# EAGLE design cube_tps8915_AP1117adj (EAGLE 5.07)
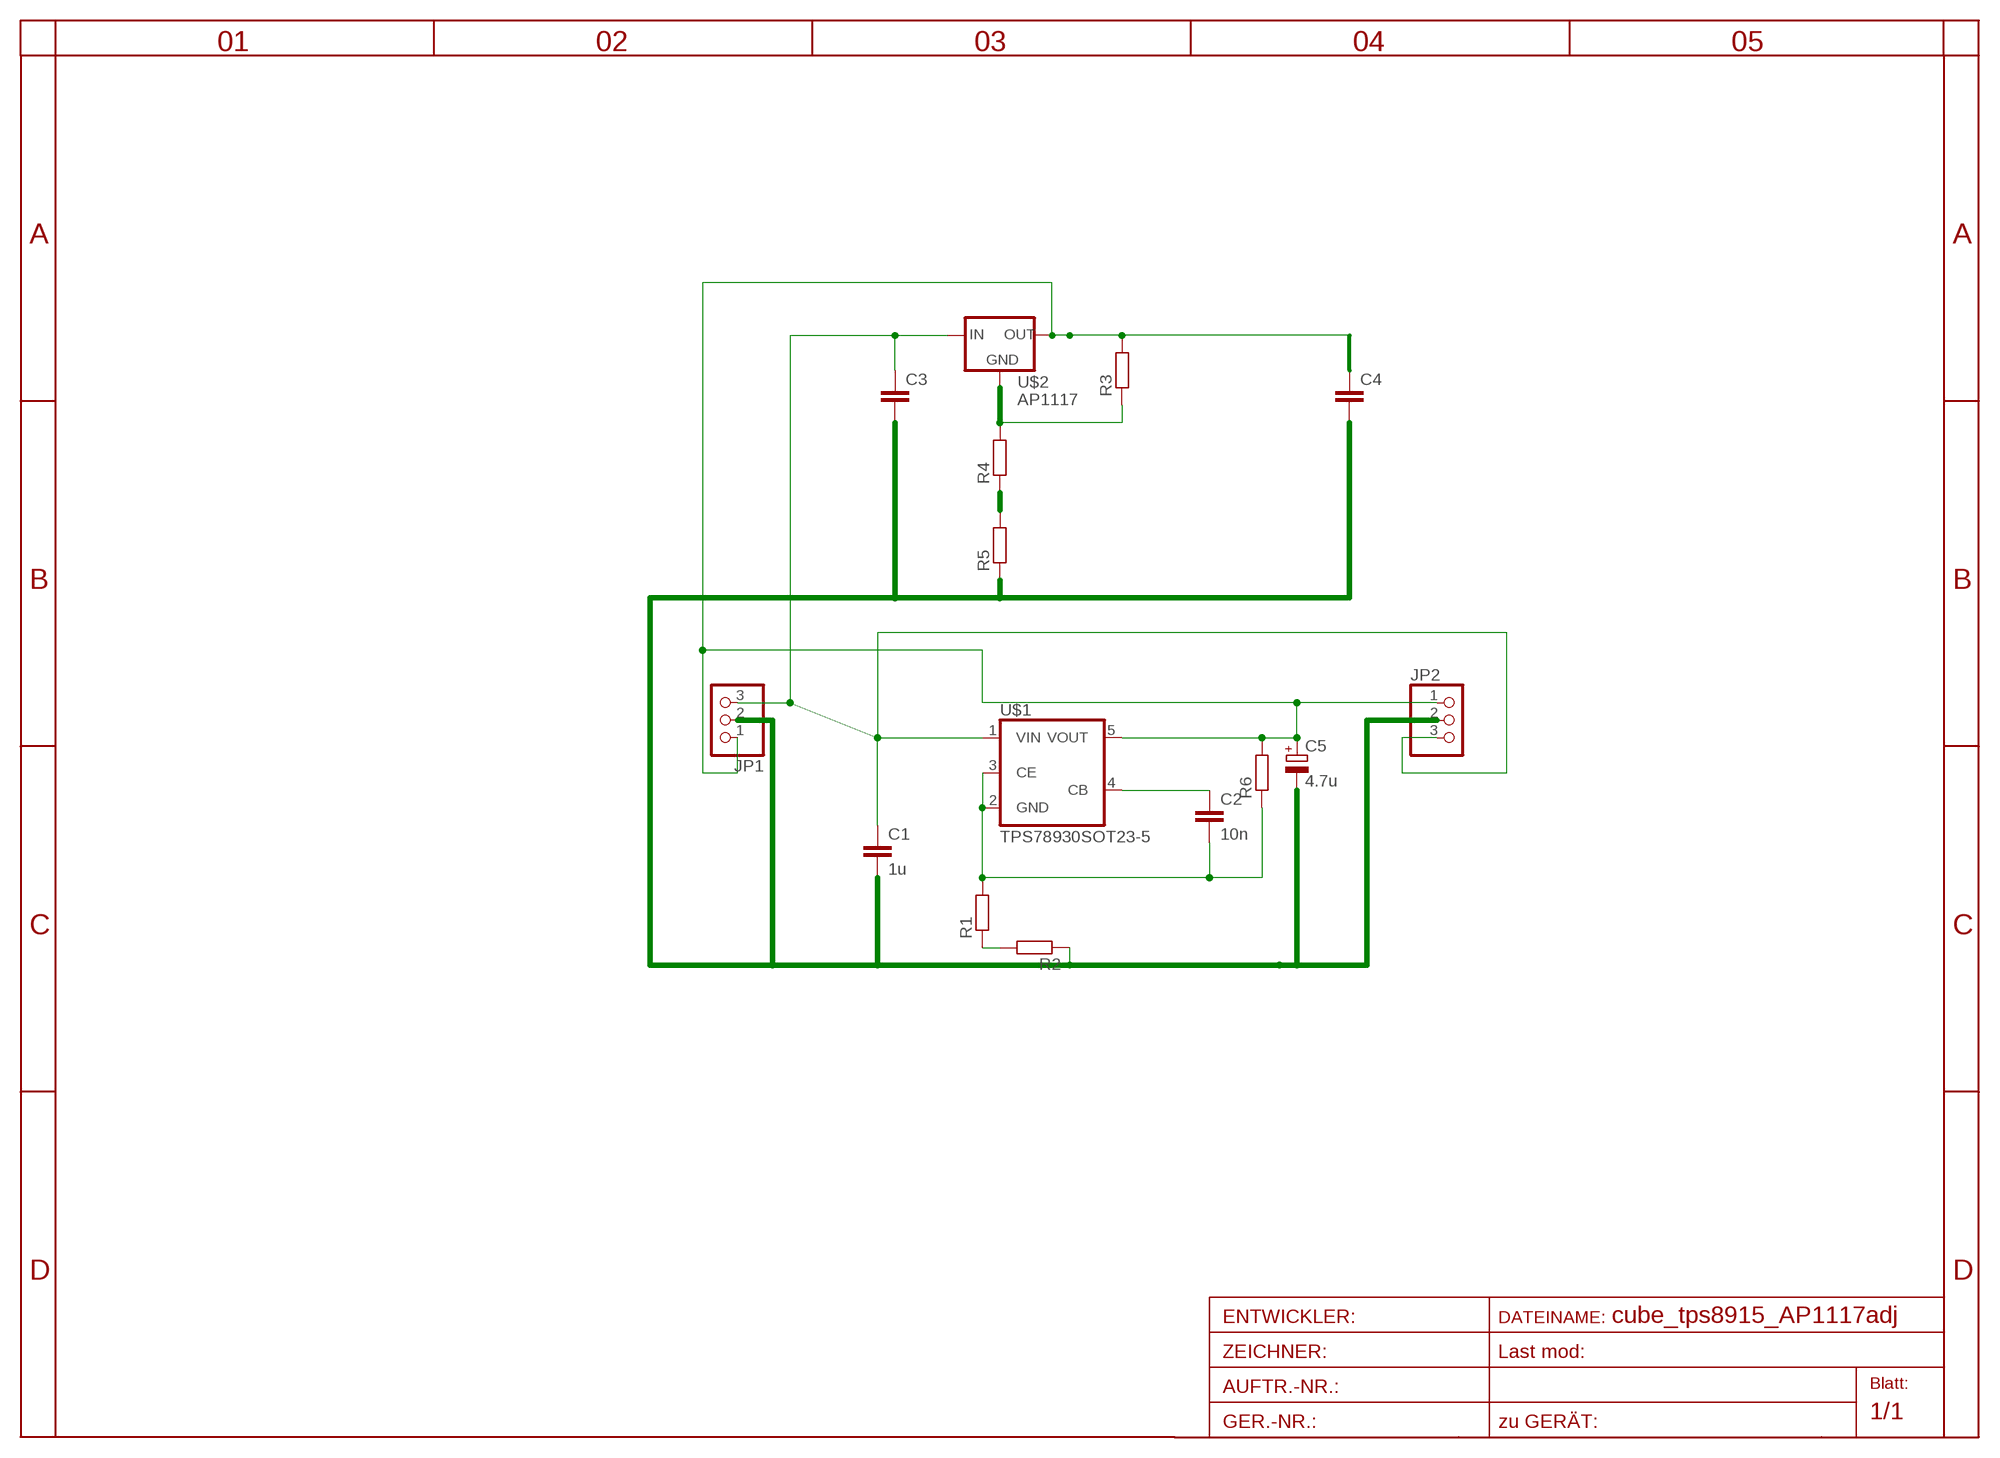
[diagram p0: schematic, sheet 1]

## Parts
C1  1u  C-EUC1206  [C1206]
C2  10n  C-EUC0805  [C0805]
C3  C-EUC1206  [C1206]
C4  C-EUC1206  [C1206]
C5  4.7u  CPOL-EUSMCA  [SMC_A]
JP1  PINHD-1X3  [1X03]
JP2  PINHD-1X3  [1X03]
R1  R-EU_R0805  [R0805]
R2  R-EU_R0805  [R0805]
R3  R-EU_R0805  [R0805]
R4  R-EU_R0805  [R0805]
R5  R-EU_R0805  [R0805]
R6  R-EU_R0805  [R0805]
U$1  TPS78930SOT23-5  [SOT25]
U$2  AP1117  [SOT223]

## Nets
GND: C1.2 C3.2 C4.2 C5.- JP1.2 JP2.2 R2.1 R5.1
IN: C1.1 C3.1 JP1.3 JP2.3 U$1.1(VIN) U$2.3(IN)
N$1: C2.1 U$1.4(CB)
N$2: C2.2 R1.2 R6.1 U$1.2(GND) U$1.3(CE)
N$3: R4.1 R5.2
N$4: R1.1 R2.2
N$5: R3.1 R4.2 U$2.1(GND)
OUT: C4.1 C5.+ JP1.1 JP2.1 R3.2 R6.2 U$1.5(VOUT) U$2.2(OUT) U$2.4(TAB)

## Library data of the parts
C1-C4 = rcl:C-EU: CAPACITOR, European symbol
C5 = rcl:CPOL-EU: POLARIZED CAPACITOR, European symbol
JP1 JP2 = pinhead:PINHD-1X3: PIN HEADER
R1-R6 = rcl:R-EU_: RESISTOR, European symbol
U$1 = v-reg:TPS78930
U$2 = v-reg:AP1117

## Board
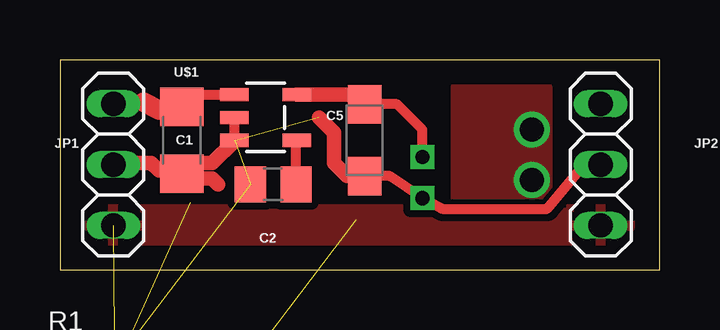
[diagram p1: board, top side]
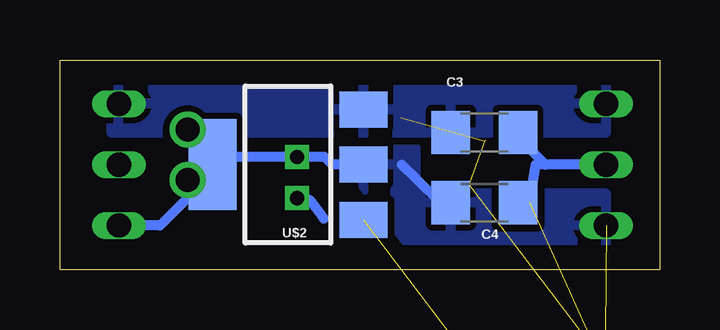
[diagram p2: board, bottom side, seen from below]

Size 25 x 8.75 mm. Coordinates in mm from the lower left corner, seen from the top.
Outline: 0,0 25,0 25,8.75 0,8.75 0,0
Copper layers (1*16): Top 0.035mm / dielectric 1.5mm / Bottom 0.035mm
Design rules "default": minimum track width 10mil, minimum drill 20mil, track to track 8mil, track to pad 8mil, pad to pad 8mil, via to via 8mil, smd to smd 8mil, copper to edge 40mil, drill to drill 8mil, minimum pad ring 1mil, minimum via ring 8mil, stop-mask expansion 4mil, vias tented up to drill 0mil, thermal gap 10mil

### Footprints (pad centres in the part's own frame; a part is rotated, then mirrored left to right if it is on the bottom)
C1206 = smd 1.6 x 1.8: 1 -1.4,0; 2 1.4,0
C0805 = smd 1.3 x 1.5: 1 -0.95,0; 2 0.95,0
SMC_A = smd 1.6 x 1.4: + -1.5,0; - 1.5,0
1X03 = drill 1.016 long: 1 -2.54,0; 2 0,0; 3 2.54,0
R0805 = smd 1.1 x 1.5: 1 -1.1,0; 2 1.1,0
SOT25 = smd 0.55 x 1.2: 1 -0.95,-1.3; 2 0,-1.3; 3 0.95,-1.3; 4 0.95,1.3; 5 -0.95,1.3
SOT223 = smd 1.5 x 2: 1 -2.3,-3.15; 2 0,-3.15; 3 2.3,-3.15 | smd 3.8 x 2: 4 0,3.15

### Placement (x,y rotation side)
C1  5.08,5.4 270 top
C2  8.89,3.56 180 top
C3  7.3,5.71 0 bottom
C4  7.3,2.79 0 bottom
C5  12.7,5.4 270 top
JP1  2.22,4.38 90 top
JP2  22.54,4.38 90 top
R1  not placed on the board
R2  not placed on the board
R3  not placed on the board
R4  not placed on the board
R5  not placed on the board
R6  not placed on the board
U$1  8.57,6.35 270 top
U$2  15.49,4.38 90 bottom

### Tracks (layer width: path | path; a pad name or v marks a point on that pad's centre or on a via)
GND  (via drill 0.6)  (3 unrouted)
  Top 0.406: 4.13,4.13 C1.2 | JP1.2 2.29,4.45 | C1.2 5.27,3.81 | C1.2 5.53,4.45 | 11.98,3.9 C5.- 13.76,3.9 v15.11,2.98 15.94,2.54 20.32,2.54 21.65,4.13 21.91,4.32 JP2.2
  Top 0.61: 4.13,4.13 3.81,4.45 2.29,4.45 | 6.6,3.56 6.35,3.81 5.27,3.81 | 7.27,5.37 6.35,4.45 5.53,4.45 | 11.98,3.9 11.43,4.45 11.43,5.71 10.79,6.35
  Bottom 0.406: C4.2 5.42,2.79 5.17,4.38 4.76,4.38 | JP1.2 4.76,4.38 | 13.99,2.13 14.58,2.9 v15.11,2.98 | C3.2 5.9,5.52 4.76,4.38
IN
  Top 0.406: 4.13,6.67 C1.1 5.71,7.3 U$1.1 | 3.49,6.99 2.29,6.99 JP1.3
  Top 0.813: 3.49,6.99 4.13,6.67
  pour Bottom (isolate 0.254): 2.22,5.71 2.22,8.26 22.86,8.26 22.86,5.71
N$1
  Top 0.406: C2.1 9.84,5.37 U$1.4
N$2  (3 unrouted)
  Top 0.406: U$1.3 U$1.2
N$3  (1 unrouted)
N$4  (1 unrouted)
N$5  (2 unrouted)
OUT  (via drill 0.6, 1)  (2 unrouted)
  Top 0.406: 12.7,7.3 C5.+ 14.06,6.9 15.11,5.84 v15.11,4.7
  Top 0.61: 12.7,7.3 U$1.5
  Bottom 0.406: C4.1 9.14,2.79 10.16,3.81 10.76,4.38 | 12.6,4.64 U$2.2 13.65,4.38 13.97,4.7 v15.11,4.7 18.33,4.7 | 18.33,4.7 18.33,4.34 20.83,1.84 JP2.1 | 18.33,4.7 U$2.4 | 18.33,4.7 18.33,4.74 v19.68,5.84
  other vias: 19.68,3.75
  pour Top (isolate 0.305, rank 2): 0.95,1.59 0.95,2.22 1.27,2.54 23.5,2.54 23.81,2.22 23.81,1.91 23.18,0.64 1.27,0.64
  pour Bottom (isolate 0.305, rank 2): 2.22,0.64 2.22,3.17 10.16,3.17 10.16,5.08 11.3,5.02 12.51,3.68 10.16,0.64
  pour Top: 16.51,7.62 20.32,7.62 20.32,2.54 16.51,2.54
